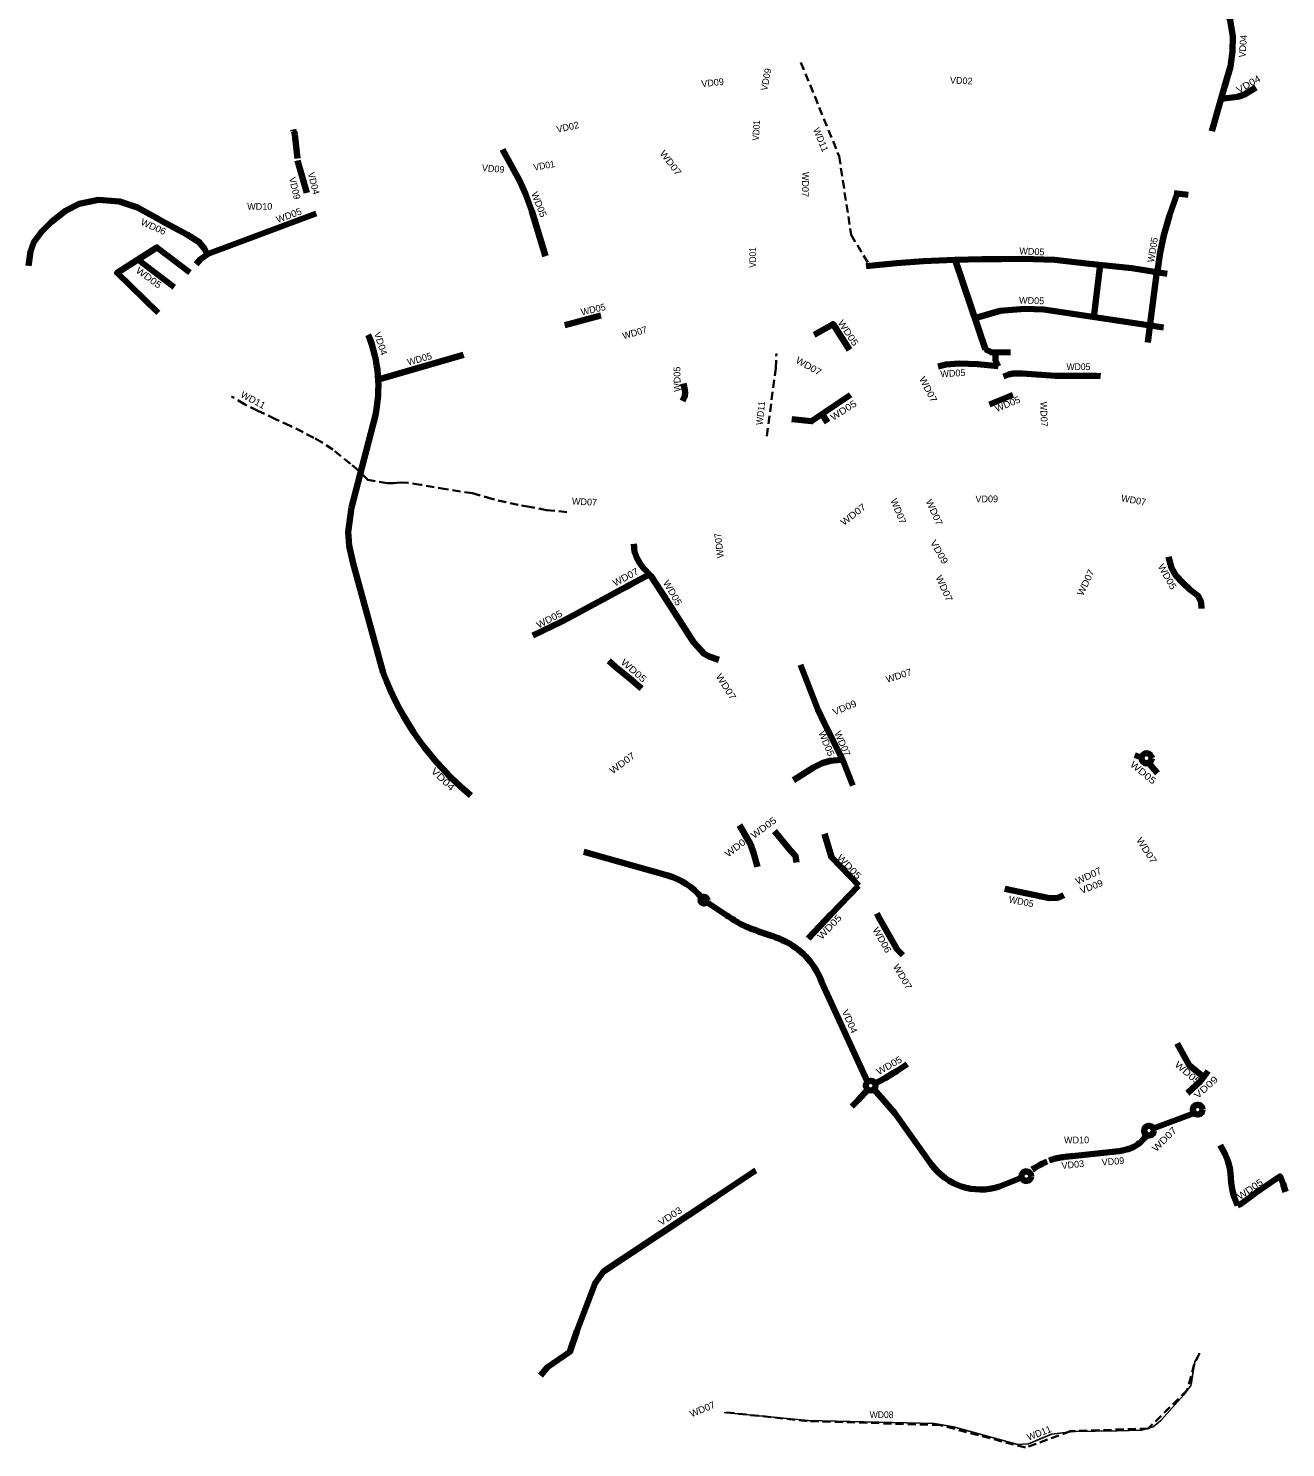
# Model space of a CAD drawing. Extents: x -650082 to -644047, y -1073232 to -1066669.
# Drawn here: x -650082 to -646363, y -1073058 to -1068858 of the extents above; entities that cross this region are included whole.
import ezdxf

# ---------------------------------------------------------------- set-up
doc = ezdxf.new("R2010")
doc.units = 0
doc.header["$LTSCALE"] = 8
doc.linetypes.add('MEDIUM_DASHED', pattern=[4.5, 3, -1.5])
for name, color, linetype in [('1', 7, 'Continuous'), ('10', 7, 'Continuous'), ('14', 7, 'Continuous'), ('15', 7, 'Continuous'), ('16', 7, 'Continuous'), ('2', 7, 'Continuous'), ('3', 7, 'Continuous'), ('4', 7, 'Continuous'), ('5', 7, 'Continuous'), ('6', 7, 'Continuous'), ('7', 7, 'Continuous'), ('9', 7, 'Continuous')]:
    doc.layers.add(name, color=color, linetype=linetype)
for name, color, linetype, lineweight in [('11', 7, 'Continuous', 106), ('12', 7, 'Continuous', 106), ('13', 7, 'MEDIUM_DASHED', 35), ('47', 7, 'Continuous', 106), ('48', 7, 'Continuous', 106), ('51', 7, 'Continuous', 106), ('52', 7, 'Continuous', 106), ('8', 7, 'Continuous', 25)]:
    doc.layers.add(name, color=color, linetype=linetype, lineweight=lineweight)

msp = doc.modelspace()

# ---------------------------------------------------------------- linework, layer by layer
at = {"layer": '11'}
for p, q in [((-649286.296, -1069243.402), (-649294.037, -1069172.192)), ((-649258.547, -1069344.39), (-649285.681, -1069249.06)), ((-649126.823, -1070275.677), (-649056.809, -1070006.786)), ((-648190.636, -1071365.392), (-648439.544, -1071295.299)), ((-647735.858, -1071680.067), (-647599.793, -1071975.634))]:
    msp.add_line(p, q, dxfattribs=at)
for points in [[(-646581.274, -1069162.086), (-646543.734, -1069031.454), (-646526.307, -1068970.81), (-646520.034, -1068926.895), (-646519.124, -1068882.525), (-646527.13, -1068833.717), (-646541.089, -1068803.463), (-646555.823, -1068777.863), (-646576.76, -1068753.039), (-646603.929, -1068734.295), (-646632.204, -1068718.474)], [(-646553.797, -1069066.473), (-646505.955, -1069060.333), (-646484.805, -1069053.474), (-646451.286, -1069033.122)], [(-649126.823, -1070275.677), (-649136.116, -1070347.82), (-649133.06, -1070389.586), (-649121.855, -1070441.538), (-649032.534, -1070765.134)], [(-648075.374, -1071443.872), (-648022.004, -1071479.581), (-648016.461, -1071483.285), (-648010.907, -1071486.974), (-648005.332, -1071490.629), (-647999.724, -1071494.234), (-647994.074, -1071497.773), (-647988.372, -1071501.227), (-647982.61, -1071504.58), (-647976.78, -1071507.812), (-647970.874, -1071510.906), (-647963.887, -1071513.957), (-647958.108, -1071516.621), (-647952.275, -1071519.164), (-647946.395, -1071521.599), (-647940.477, -1071523.938), (-647934.527, -1071526.195), (-647928.551, -1071528.382), (-647922.556, -1071530.515), (-647916.545, -1071532.605), (-647910.525, -1071534.668), (-647904.5, -1071536.717), (-647895.595, -1071539.745), (-647889.576, -1071541.81), (-647883.568, -1071543.908), (-647877.578, -1071546.054), (-647871.61, -1071548.265), (-647865.673, -1071550.555), (-647859.774, -1071552.942), (-647853.921, -1071555.438), (-647848.123, -1071558.061), (-647842.39, -1071560.823), (-647836.733, -1071563.738)]]:
    msp.add_lwpolyline(points, dxfattribs=at)
msp.add_circle((-648083.781, -1071438.172), 10.157, dxfattribs=at)
for centre, radius, start, end in [((-649390.897, -1069197.054), 100, 14.39558, 23.46117), ((-649452.625, -1069917.995), 405.652, 347.35635, 22.18649), ((-648232.695, -1070467.567), 853.398, 200.40686, 230.69896), ((-648244.965, -1071557.871), 200, 39.49461, 74.23772), ((-647937.958, -1071753.418), 215, 19.9479, 61.91292)]:
    msp.add_arc(centre, radius, start, end, dxfattribs=at)
at = {"layer": '12'}
for p, q in [((-646754.674, -1072114.023), (-646633.694, -1072068.165)), ((-646993.404, -1072195.535), (-646875.615, -1072182.532)), ((-647145.028, -1072259.442), (-647209.69, -1072285.315))]:
    msp.add_line(p, q, dxfattribs=at)
for points in [[(-647646.641, -1072049.031), (-647627.876, -1072030.328), (-647598.733, -1071998.754)], [(-647581.398, -1071997.866), (-647544.374, -1072039.387), (-647519.615, -1072068.332), (-647409.551, -1072222.875)], [(-647062.642, -1072208.565), (-647057.907, -1072206.959), (-647053.125, -1072205.5), (-647048.303, -1072204.179), (-647043.448, -1072202.984), (-647038.565, -1072201.905), (-647033.661, -1072200.931), (-647028.739, -1072200.051), (-647023.804, -1072199.253), (-647018.857, -1072198.525), (-647013.902, -1072197.856), (-647008.941, -1072197.235), (-647003.975, -1072196.649), (-646999.007, -1072196.086), (-646994.037, -1072195.536)], [(-646876.248, -1072183.165), (-646872.383, -1072182.737), (-646868.519, -1072182.3), (-646864.657, -1072181.844), (-646860.798, -1072181.36), (-646856.944, -1072180.839), (-646853.097, -1072180.272), (-646849.258, -1072179.649), (-646845.43, -1072178.963), (-646841.617, -1072178.202), (-646837.82, -1072177.36), (-646834.045, -1072176.427), (-646830.296, -1072175.394), (-646826.578, -1072174.254), (-646822.898, -1072172.998), (-646819.262, -1072171.619), (-646815.677, -1072170.111), (-646812.154, -1072168.466), (-646808.701, -1072166.678)], [(-647930.391, -1072238.053), (-647936.91, -1072242.12), (-648048.17, -1072316.094), (-648380.845, -1072537.281), (-648405.937, -1072571.667), (-648460.352, -1072713.39), (-648480.403, -1072774.677), (-648546.627, -1072820.111), (-648567.38, -1072844.77)], [(-647112.659, -1072235.417), (-647108.405, -1072232.79), (-647104.143, -1072230.176), (-647099.863, -1072227.591), (-647095.557, -1072225.05), (-647091.218, -1072222.565), (-647086.838, -1072220.154), (-647082.411, -1072217.83), (-647077.93, -1072215.611), (-647073.393, -1072213.512), (-647068.794, -1072211.549)]]:
    msp.add_lwpolyline(points, dxfattribs=at)
for centre in [(-647590.655, -1071986.8), (-646623.358, -1072058.099), (-646767.624, -1072120.384), (-647130.12, -1072255.012)]:
    msp.add_circle(centre, 14.428, dxfattribs=at)
for centre, radius, start, end in [((-646851.756, -1072087.012), 90, 298.5808, 324.78461), ((-647266.212, -1072116.452), 178.071, 215.23547, 288.50636)]:
    msp.add_arc(centre, radius, start, end, dxfattribs=at)
at = {"layer": '13'}
for points in [[(-647796.971, -1068958.769), (-647683.968, -1069236.597), (-647648.396, -1069468.745), (-647594.062, -1069560.317), (-647340.265, -1069541.717), (-647253.655, -1069810.08), (-647231.91, -1069823.971)], [(-647897.53, -1070064.61), (-647871.671, -1069864.156), (-647869.45, -1069820.63)], [(-648489.42, -1070289.79), (-648549.11, -1070283.64), (-648599.41, -1070274.03), (-648633.75, -1070268.38), (-648711.24, -1070250.44), (-648768.32, -1070233.86), (-648846.76, -1070222.17), (-648921.87, -1070208.67), (-648959.67, -1070203.09), (-648981.35, -1070202.4), (-649002.23, -1070203.94), (-649021.05, -1070203.56), (-649078.099, -1070194.501), (-649106.06, -1070166.8), (-649129.57, -1070146.73), (-649181.7, -1070104.45), (-649213.21, -1070083.53), (-649237.78, -1070069.79), (-649307.84, -1070034.18), (-649351.66, -1070014.26), (-649403.65, -1069989.85), (-649442.47, -1069970.36), (-649481, -1069947.32)], [(-646618.098, -1072779.957), (-646633.878, -1072812.319), (-646654.064, -1072888.773), (-646770.097, -1073001.842), (-647000.119, -1073009.906), (-647132.968, -1073058.363), (-647385.213, -1072991.734), (-647778.715, -1072979.619), (-648025.915, -1072953.371)]]:
    msp.add_lwpolyline(points, dxfattribs=at)
at = {"layer": '47'}
for p, q in [((-646692.985, -1069346.026), (-646651.217, -1069350.274)), ((-647339.967, -1069545.744), (-647251.088, -1069808.426)), ((-646912.03, -1069558.076), (-646930.389, -1069712.594)), ((-648494.915, -1069736.521), (-648388.804, -1069707.486)), ((-647207.164, -1069694.062), (-647282.295, -1069716.194)), ((-649043.757, -1069896.46), (-648795.401, -1069824.199)), ((-647170.402, -1069942.221), (-647239.362, -1069971.673)), ((-647718.115, -1070024.038), (-647733.777, -1069999.441)), ((-647672.743, -1071023.641), (-647643.873, -1071098.745)), ((-646808.839, -1071008.864), (-646795.926, -1071014.301)), ((-647824.318, -1071296.38), (-647875.239, -1071233.632)), ((-647708.122, -1071480.45), (-647626.882, -1071395.872)), ((-647708.122, -1071480.45), (-647775.697, -1071551.243))]:
    msp.add_line(p, q, dxfattribs=at)
for points in [[(-648552.408, -1069532.362), (-648592.697, -1069398.642), (-648611.424, -1069347.704), (-648629.402, -1069308.002), (-648679.548, -1069216.178)], [(-646742.322, -1069576.725), (-646734.087, -1069520.908), (-646723.107, -1069469.667), (-646706.636, -1069412.02), (-646684.285, -1069346.911)], [(-649586.177, -1069556.212), (-649573.053, -1069541.298), (-649550.047, -1069525.713), (-649230.786, -1069405.644)], [(-647603.51, -1069561.425), (-647514.414, -1069553.281), (-647434.342, -1069547.122), (-647341.331, -1069542.596), (-647262.07, -1069540.647), (-647204.248, -1069540.647), (-647140.134, -1069540.07), (-647047.049, -1069543.256), (-646943.2, -1069554.795), (-646817.923, -1069567.982), (-646714.075, -1069584.466)], [(-646744.044, -1069579.015), (-646764.641, -1069739.238), (-646770.927, -1069787.596)], [(-646724.352, -1069743.581), (-647078.839, -1069690.268), (-647135.789, -1069688.123), (-647207.164, -1069694.062)], [(-647757.476, -1069764.575), (-647701.982, -1069733.103), (-647653.087, -1069809.089)], [(-647390.821, -1069859.073), (-647368.021, -1069852.558), (-647328.004, -1069849.767), (-647274.492, -1069852.093), (-647213.899, -1069857.686)], [(-647251.088, -1069808.426), (-647232.613, -1069816.264), (-647177.241, -1069817.194)], [(-647213.795, -1069859.205), (-647220.933, -1069841.605), (-647221.408, -1069819.284)], [(-647197.567, -1069888.373), (-647182.853, -1069882.067), (-647168.927, -1069879.439), (-647141.6, -1069879.965), (-647044.065, -1069885.918), (-646922.882, -1069885.918), (-646911.17, -1069886.938)], [(-648147.091, -1069960.576), (-648140.266, -1069946.926), (-648139.508, -1069934.035), (-648144.058, -1069909.01)], [(-647650.097, -1069942.883), (-647765.549, -1070020.915), (-647823.598, -1070014.961)], [(-648290.966, -1070383.374), (-648288.845, -1070406.899), (-648282.079, -1070425.044), (-648273.16, -1070440.728), (-648264.17, -1070453.236), (-648241.202, -1070478.118), (-648211.195, -1070523.918)], [(-646709.343, -1070422.319), (-646700.372, -1070454.216), (-646687.863, -1070477.44), (-646666.258, -1070500.316), (-646645.289, -1070519.379), (-646621.777, -1070537.807), (-646613.517, -1070556.235), (-646612.246, -1070574.663)], [(-648589.664, -1070655.082), (-648504.268, -1070613.585), (-648469.046, -1070594.986), (-648434.122, -1070576.22), (-648370.201, -1070541.371), (-648326.641, -1070517.498), (-648313.175, -1070510.435), (-648300.652, -1070503.633), (-648244.358, -1070473.301)], [(-648039.532, -1070726.638), (-648068.169, -1070717.378), (-648082.709, -1070709.44), (-648115.092, -1070674.163), (-648211.195, -1070523.918)], [(-648268.369, -1070811.262), (-648303.087, -1070781.942), (-648344.753, -1070748.129), (-648364.772, -1070729.983)], [(-647798.303, -1070741.695), (-647747.4, -1070874.36), (-647727.829, -1070913.158), (-647672.743, -1071023.641)], [(-647677.55, -1071022.921), (-647710.774, -1071025.971), (-647733.735, -1071032.504), (-647759.543, -1071045.17), (-647818.707, -1071082.607)], [(-646741.751, -1071062.202), (-646751.573, -1071052.898), (-646766.082, -1071034.526)], [(-647925.368, -1071339.891), (-647936.852, -1071298.253), (-647946.561, -1071272.093), (-647978.731, -1071216.254)], [(-647727.338, -1071242.207), (-647706.62, -1071310.667), (-647625.686, -1071394.72)], [(-647810.393, -1071327.127), (-647812.572, -1071307.894), (-647823.337, -1071295.659)], [(-647193.49, -1071404.445), (-647061.509, -1071431.827), (-647037.352, -1071430.861), (-647019.146, -1071423.327)], [(-646684.409, -1071862), (-646648.676, -1071926.01), (-646609.296, -1071959.529)], [(-647577.687, -1071980.477), (-647548.027, -1071965.02), (-647528.6, -1071953.175), (-647512.49, -1071943.224), (-647482.989, -1071923.852)], [(-646592.707, -1071943.76), (-646614.335, -1071972.381), (-646653.429, -1072008.981)], [(-646556.924, -1072163.008), (-646541.975, -1072190.142), (-646534.08, -1072209.348), (-646528.451, -1072231.169), (-646526.022, -1072245.895), (-646524.078, -1072274.419), (-646520.515, -1072298.567), (-646515.575, -1072317.043), (-646505.446, -1072341.949)], [(-646505.446, -1072341.949), (-646496.463, -1072338.193), (-646468.402, -1072317.124), (-646451.071, -1072304.158), (-646409.932, -1072275.634), (-646379.686, -1072255.456), (-646370.251, -1072277.255), (-646363.282, -1072301.269)]]:
    msp.add_lwpolyline(points, dxfattribs=at)
msp.add_circle((-646774.452, -1071018.284), 15.055, dxfattribs=at)
at = {"layer": '48'}
msp.add_line((-649650.964, -1069624.206), (-649758.457, -1069542.558), dxfattribs=at)
msp.add_lwpolyline([(-649698.475, -1069700.198), (-649819.737, -1069581.875), (-649701.821, -1069506.22), (-649604.8, -1069580.077)], dxfattribs=at)
at = {"layer": '51'}
for points in [[(-649690.862, -1069426.602), (-649693.075, -1069424.839), (-649759.229, -1069388.516), (-649812.457, -1069370.063), (-649874.912, -1069365.805), (-649931.689, -1069377.161), (-649972.852, -1069398.452), (-650014.541, -1069431.96), (-650043.673, -1069460), (-650065.774, -1069491.142), (-650076.339, -1069518.627), (-650082.165, -1069560.934)], [(-647572.568, -1071477.763), (-647563.965, -1071494.251), (-647512.351, -1071583.86), (-647495.989, -1071600.795)]]:
    msp.add_lwpolyline(points, dxfattribs=at)
at = {"layer": '52'}
msp.add_lwpolyline([(-649553.361, -1069527.958), (-649560.675, -1069511.85), (-649576.968, -1069490.717), (-649611.664, -1069468.981), (-649690.862, -1069426.602)], dxfattribs=at)
at = {"layer": '8'}
for points in [[(-646641.615, -1072861.847), (-646642.788, -1072871.592), (-646636.323, -1072833.305), (-646631.944, -1072804.277), (-646618.055, -1072778.52)], [(-648023.648, -1072953.961), (-647775.451, -1072978.577), (-647402.33, -1072986.644), (-647345.858, -1072996.728), (-647156.272, -1073049.167), (-647124.002, -1073047.15), (-647055.429, -1073018.914), (-646990.889, -1073010.846), (-646861.81, -1073008.83), (-646789.202, -1073006.813), (-646754.915, -1072996.728), (-646732.73, -1072978.577), (-646664.156, -1072901.935), (-646642.762, -1072873.366)]]:
    msp.add_lwpolyline(points, dxfattribs=at)

# ---------------------------------------------------------------- texts
at = {"layer": '1'}
for rotation, width, p in [(86.772, 0.9, (-647921.103, -1069190.627)), (9.97, 0.95, (-648586.178, -1069279.341)), (90.083, 0.9, (-647929.691, -1069566.304))]:
    msp.add_text('VD01', height=20, rotation=rotation, dxfattribs=dict(at, width=width)).set_placement(p)
at = {"layer": '10'}
for p in [(-649434.865, -1069395.02), (-647018.705, -1072158.017)]:
    msp.add_text('WD10', height=20, rotation=0.318, dxfattribs=at).set_placement(p)
at = {"layer": '14'}
for rotation, p in [(292.311, (-647761.508, -1069157.121)), (20.83, (-647123.491, -1073037.925))]:
    msp.add_text('WD11', height=20, rotation=rotation, dxfattribs=at).set_placement(p)
for rotation, width, p in [(332.078, 1.05, (-649456.64, -1069948.265)), (83.81, 0.95, (-647910.311, -1070032.951))]:
    msp.add_text('WD11', height=20, rotation=rotation, dxfattribs=dict(at, width=width)).set_placement(p)
at = {"layer": '15', "width": 1.15}
msp.add_text('WD05', height=20, rotation=323.794, dxfattribs=at).set_placement((-649766.25, -1069578.722))
at = {"layer": '16', "width": 1.05}
msp.add_text('WD06', height=20, rotation=336.373, dxfattribs=at).set_placement((-649751.99, -1069438.856))
at = {"layer": '2'}
for rotation, p in [(357.375, (-647356.457, -1069021.082)), (12.542, (-648517.473, -1069167.221))]:
    msp.add_text('VD02', height=20, rotation=rotation, dxfattribs=at).set_placement(p)
at = {"layer": '3'}
msp.add_text('VD03', height=20, rotation=6.009, dxfattribs=at).set_placement((-647025.037, -1072234.169))
at = {"layer": '3', "width": 1.15}
msp.add_text('VD03', height=20, rotation=33.391, dxfattribs=at).set_placement((-648210.42, -1072403.064))
at = {"layer": '4'}
for rotation, p in [(85.893, (-646482.108, -1068944.939)), (284.235, (-649256.065, -1069286.662))]:
    msp.add_text('VD04', height=20, rotation=rotation, dxfattribs=at).set_placement(p)
for rotation, width, p in [(29.411, 1.15, (-646502.014, -1069050.708)), (287.6, 1.05, (-649060.021, -1069760.208)), (316.159, 1.25, (-648893.138, -1071058.344)), (293.494, 1.1, (-647676.428, -1071767.021))]:
    msp.add_text('VD04', height=20, rotation=rotation, dxfattribs=dict(at, width=width)).set_placement(p)
at = {"layer": '5'}
for rotation, width, p in [(291.57, 1.05, (-648595.322, -1069346.682)), (20.413, 1.05, (-649344.656, -1069434.505)), (303.586, 1.15, (-647689.055, -1069729.375)), (359.771, 0.95, (-647011.407, -1069869.205)), (32.763, 1.15, (-647701.559, -1070019.86)), (22.562, 1.05, (-647217.993, -1069994.051)), (299.409, 1.1, (-646742.052, -1070450.235)), (300.371, 1.1, (-648205.967, -1070498.405)), (27.93, 1.1, (-648572.628, -1070634.584)), (318.812, 1.2, (-648331.556, -1070736.821)), (292.87, 1.05, (-647745.74, -1070942.497)), (320.604, 1.2, (-646825.309, -1071040.045)), (36.91, 1.15, (-647935.396, -1071257.441)), (313.863, 1.2, (-647692.262, -1071314.022)), (46.414, 1.2, (-647735.69, -1071556.53)), (29.944, 1.1, (-647566.364, -1071956.55)), (319.129, 1.2, (-646693.266, -1071927.68)), (34.487, 1.15, (-646498.118, -1072326.083))]:
    msp.add_text('WD05', height=20, rotation=rotation, dxfattribs=dict(at, width=width)).set_placement(p)
for rotation, p in [(357.197, (-647151.356, -1069526.302)), (80.615, (-646752.852, -1069551.846)), (12.814, (-648445.492, -1069707.786)), (358.177, (-647151.994, -1069672.198)), (15.559, (-648958.337, -1069856.049)), (90.808, (-648152.699, -1069933.435)), (2.857, (-647383.984, -1069890.409)), (348.607, (-647183.65, -1071444.769))]:
    msp.add_text('WD05', height=20, rotation=rotation, dxfattribs=at).set_placement(p)
at = {"layer": '6', "width": 1.1}
msp.add_text('WD06', height=20, rotation=299.586, dxfattribs=at).set_placement((-647586.001, -1071525.44))
at = {"layer": '7'}
for rotation, width, p in [(307.201, 1.15, (-648216.084, -1069228.211)), (330.302, 1.1, (-647814.4, -1069846.044)), (297.667, 1.1, (-647448.246, -1069895.109)), (37.889, 1.15, (-647669.893, -1070330.992)), (292.116, 1.05, (-647532.629, -1070254.406)), (294.454, 1.1, (-647428.465, -1070257.434)), (28.414, 1.1, (-648346.892, -1070510.452)), (294.454, 1.1, (-647399.207, -1070482.213)), (64.535, 1.1, (-646963.014, -1070539.33)), (302.302, 1.15, (-648049.847, -1070775.71)), (17.803, 1.05, (-647541.835, -1070795.135)), (293.26, 1.05, (-647698.608, -1070943.099)), (36.212, 1.15, (-648354.157, -1071065.604)), (37.876, 1.15, (-648012.3, -1071312.413)), (302.643, 1.15, (-646805.959, -1071260.156)), (25.46, 1.1, (-646978.911, -1071392.769)), (299.885, 1.1, (-647525.38, -1071634.155)), (45.026, 1.2, (-646746.182, -1072184.521)), (22.432, 1.05, (-648120.604, -1072968.926))]:
    msp.add_text('WD07', height=20, rotation=rotation, dxfattribs=dict(at, width=width)).set_placement(p)
for rotation, p in [(269.034, (-647793.034, -1069282.646)), (16.02, (-648321.58, -1069778.479)), (272.013, (-647089.498, -1069963.268)), (357.034, (-648474.765, -1070267.044)), (349.845, (-646850.986, -1070257.62)), (97.026, (-648024.784, -1070424.219))]:
    msp.add_text('WD07', height=20, rotation=rotation, dxfattribs=at).set_placement(p)
at = {"layer": '8', "width": 0.95}
msp.add_text('WD08', height=20, rotation=359.822, dxfattribs=at).set_placement((-647593.734, -1072970.888))
at = {"layer": '9'}
for rotation, p in [(6.253, (-648090.523, -1069032.33)), (78.961, (-647896.883, -1069044.007)), (355.112, (-648741.445, -1069280.24)), (283.42, (-649311.686, -1069300.906)), (0.216, (-647280.667, -1070260.641)), (4.69, (-646906.544, -1072223.962))]:
    msp.add_text('VD09', height=20, rotation=rotation, dxfattribs=at).set_placement(p)
for rotation, width, p in [(299.658, 1.15, (-647415.603, -1070379.066)), (22.494, 1.1, (-647698.244, -1070891.729)), (20.79, 1.05, (-646967.13, -1071419.926)), (41.768, 1.25, (-646623.484, -1072027.315))]:
    msp.add_text('VD09', height=20, rotation=rotation, dxfattribs=dict(at, width=width)).set_placement(p)

doc.saveas('drawing.dxf')
